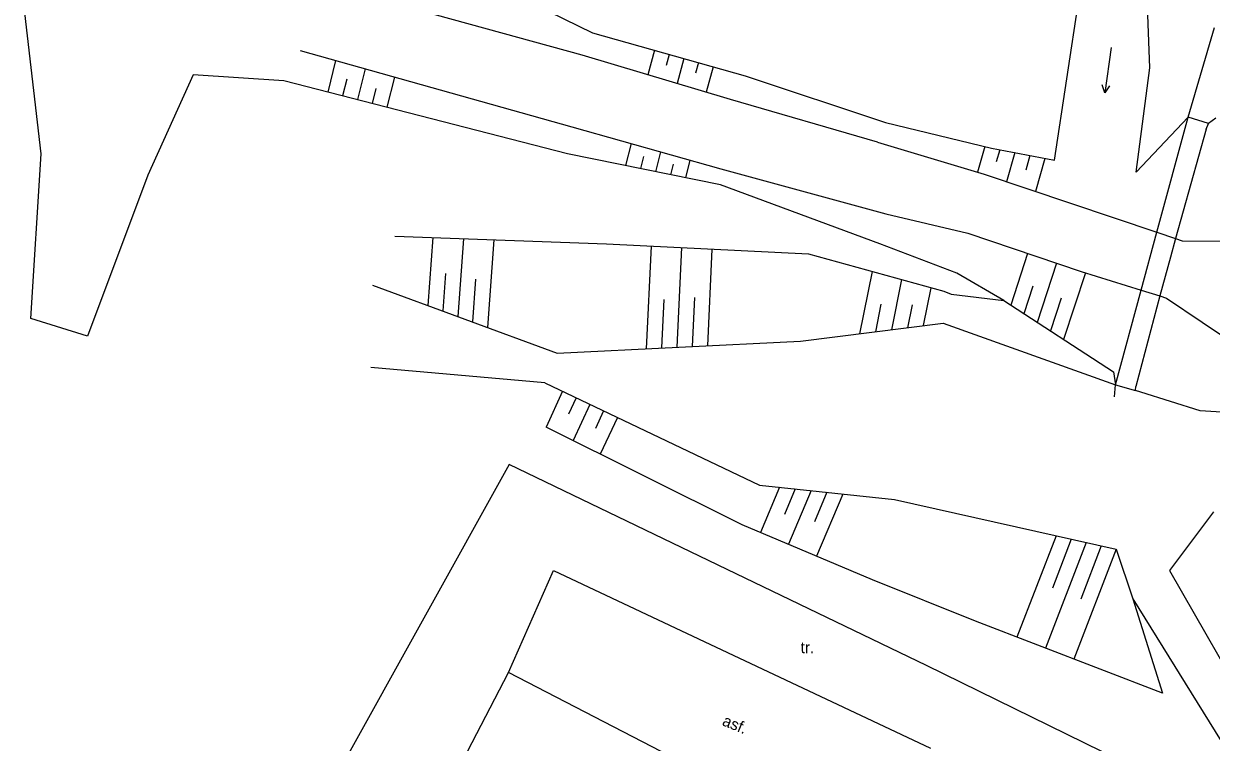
# Model space of a CAD drawing. Extents: x -794191 to -788944, y -1117087 to -1105044.
# Drawn here: x -790359.9 to -790282, y -1111834.4 to -1111787.2 of the extents above; entities that cross this region are included whole.
import ezdxf

# ---------------------------------------------------------------- set-up
doc = ezdxf.new("R2010")
doc.units = 0
for name, color, linetype in [('Doplněk polohopisu', 7, 'Continuous'), ('Hranice - ploty_ zdi', 7, 'Continuous'), ('Komunikace', 7, 'Continuous'), ('Pomocné popisy', 7, 'Continuous'), ('Stavební objekty', 7, 'Continuous'), ('Výškopis', 7, 'Continuous'), ('Značky druhů pozemků', 7, 'Continuous')]:
    doc.layers.add(name, color=color, linetype=linetype)

msp = doc.modelspace()

# ---------------------------------------------------------------- linework, layer by layer
at = {"layer": 'Doplněk polohopisu'}
for p, q in [((-790299.53, -1111804.77), (-790299.05, -1111804.96)), ((-790299.05, -1111804.96), (-790295.6, -1111805.38))]:
    msp.add_line(p, q, dxfattribs=at)
at = {"layer": 'Hranice - ploty_ zdi'}
for p, q in [((-790283.5, -1111793.35), (-790281.76, -1111787.46)), ((-790288.26, -1111810.91), (-790286.95, -1111811.28)), ((-790286.95, -1111811.28), (-790286.92, -1111811.01)), ((-790328.05, -1111816.14), (-790344.67, -1111845.99)), ((-790300.68, -1111829.32), (-790328.05, -1111816.14)), ((-790282.07, -1111838.44), (-790300.68, -1111829.32))]:
    msp.add_line(p, q, dxfattribs=at)
for points in [[(-790288.32, -1111811.7), (-790288.26, -1111810.91), (-790286.57, -1111804.7), (-790285.56, -1111800.88), (-790283.5, -1111793.35)], [(-790282.32, -1111794.13), (-790282.15, -1111793.76), (-790283.5, -1111793.35)], [(-790282.32, -1111794.13), (-790284.32, -1111801.3), (-790284.66, -1111802.53)], [(-790284.66, -1111802.53), (-790285.36, -1111805.07), (-790286.92, -1111811.01)]]:
    msp.add_lwpolyline(points, dxfattribs=at)
at = {"layer": 'Komunikace'}
msp.add_line((-790287.12, -1111824.96), (-790281.32, -1111834.29), dxfattribs=at)
for points in [[(-790281.84, -1111819.25), (-790284.71, -1111823.1), (-790279.09, -1111832.9)], [(-790328.11, -1111829.78), (-790325.14, -1111823.09), (-790300.4, -1111834.76)]]:
    msp.add_lwpolyline(points, dxfattribs=at)
at = {"layer": 'Stavební objekty'}
msp.add_line((-790339.54, -1111851.86), (-790328.11, -1111829.78), dxfattribs=at)
msp.add_lwpolyline([(-790339.54, -1111851.86), (-790329.07, -1111857.3), (-790328.18, -1111857.64), (-790325.33, -1111852.24), (-790319.61, -1111841.2), (-790316.82, -1111835.63), (-790328.11, -1111829.78)], dxfattribs=at)
at = {"layer": 'Výškopis'}
for p, q in [((-790292.26, -1111796.17), (-790289.79, -1111779.85)), ((-790286.02, -1111790.1), (-790286.31, -1111781.72)), ((-790323.27, -1111789.28), (-790340.36, -1111784.56)), ((-790358.77, -1111795.75), (-790359.92, -1111785.93)), ((-790327.38, -1111785.46), (-790322.58, -1111787.81)), ((-790322.58, -1111787.81), (-790312.56, -1111790.62)), ((-790341.77, -1111788.97), (-790323.94, -1111793.98)), ((-790318.53, -1111788.95), (-790318.96, -1111790.56)), ((-790339.45, -1111789.62), (-790339.96, -1111791.69)), ((-790313.54, -1111792.18), (-790323.27, -1111789.28)), ((-790317.56, -1111789.22), (-790317.76, -1111789.94)), ((-790316.6, -1111789.49), (-790317.04, -1111791.14)), ((-790315.64, -1111789.76), (-790315.82, -1111790.45)), ((-790348.8, -1111790.57), (-790351.78, -1111797.14)), ((-790342.85, -1111790.95), (-790348.8, -1111790.57)), ((-790337.52, -1111790.16), (-790338.02, -1111792.19)), ((-790335.59, -1111790.71), (-790336.09, -1111792.69)), ((-790314.67, -1111790.03), (-790315.12, -1111791.71)), ((-790312.56, -1111790.62), (-790303.35, -1111793.68)), ((-790286.91, -1111796.96), (-790286.02, -1111790.1)), ((-790324.24, -1111795.74), (-790342.85, -1111790.95)), ((-790338.72, -1111790.84), (-790338.99, -1111791.94)), ((-790336.81, -1111791.45), (-790337.06, -1111792.44)), ((-790303.88, -1111794.98), (-790313.54, -1111792.18)), ((-790303.35, -1111793.68), (-790296.41, -1111795.38)), ((-790286.91, -1111796.96), (-790283.5, -1111793.35)), ((-790281.68, -1111793.41), (-790282.15, -1111793.76)), ((-790323.94, -1111793.98), (-790314.16, -1111796.73)), ((-790320.06, -1111795.07), (-790320.42, -1111796.52)), ((-790303.88, -1111794.98), (-790296.88, -1111797.09)), ((-790296.84, -1111795.27), (-790297.32, -1111796.96)), ((-790296.41, -1111795.38), (-790292.26, -1111796.17)), ((-790359.46, -1111806.55), (-790358.77, -1111795.75)), ((-790314.18, -1111797.79), (-790324.24, -1111795.74)), ((-790319.24, -1111795.93), (-790319.44, -1111796.72)), ((-790318.13, -1111795.61), (-790318.46, -1111796.92)), ((-790316.2, -1111796.16), (-790316.49, -1111797.32)), ((-790295.86, -1111795.48), (-790296.09, -1111796.27)), ((-790294.88, -1111795.67), (-790295.42, -1111797.58)), ((-790293.89, -1111795.86), (-790294.16, -1111796.81)), ((-790292.91, -1111796.05), (-790293.52, -1111798.22)), ((-790317.3, -1111796.42), (-790317.47, -1111797.12)), ((-790314.16, -1111796.73), (-790303.33, -1111799.68)), ((-790351.78, -1111797.14), (-790355.73, -1111807.72)), ((-790303.73, -1111801.65), (-790314.18, -1111797.79)), ((-790303.33, -1111799.68), (-790297.95, -1111800.96)), ((-790335.57, -1111801.15), (-790321.68, -1111801.66)), ((-790333.07, -1111801.24), (-790333.39, -1111805.7)), ((-790331.06, -1111801.32), (-790331.44, -1111806.42)), ((-790329.06, -1111801.39), (-790329.49, -1111807.14)), ((-790297.95, -1111800.96), (-790290.52, -1111803.46)), ((-790283.89, -1111801.45), (-790277.7, -1111801.5)), ((-790321.68, -1111801.66), (-790308.42, -1111802.31)), ((-790318.74, -1111801.8), (-790319.06, -1111808.54)), ((-790316.75, -1111801.9), (-790317.05, -1111808.44)), ((-790314.75, -1111802), (-790315.04, -1111808.34)), ((-790308.42, -1111802.31), (-790299.53, -1111804.77)), ((-790298.67, -1111803.57), (-790303.73, -1111801.65)), ((-790294.04, -1111802.28), (-790295.14, -1111805.68)), ((-790292.14, -1111802.92), (-790293.41, -1111806.81)), ((-790332.24, -1111803.61), (-790332.42, -1111806.06)), ((-790304.24, -1111803.47), (-790305.06, -1111807.56)), ((-790295.6, -1111805.38), (-790298.67, -1111803.57)), ((-790290.24, -1111803.55), (-790291.67, -1111807.93)), ((-790337.03, -1111804.37), (-790324.9, -1111808.82)), ((-790330.26, -1111803.98), (-790330.46, -1111806.78)), ((-790302.31, -1111804), (-790302.97, -1111807.29)), ((-790300.38, -1111804.54), (-790300.88, -1111807.02)), ((-790293.68, -1111804.43), (-790294.27, -1111806.24)), ((-790317.91, -1111805.31), (-790318.06, -1111808.49)), ((-790315.9, -1111805.18), (-790316.05, -1111808.39)), ((-790295.6, -1111805.38), (-790288.4, -1111810.06)), ((-790291.84, -1111805.23), (-790292.54, -1111807.37)), ((-790284.92, -1111805.21), (-790280.12, -1111808.46)), ((-790303.66, -1111805.61), (-790304.02, -1111807.42)), ((-790301.62, -1111805.66), (-790301.92, -1111807.16)), ((-790355.73, -1111807.72), (-790359.46, -1111806.55)), ((-790308.93, -1111808.05), (-790299.58, -1111806.86)), ((-790299.58, -1111806.86), (-790288.26, -1111810.91)), ((-790324.9, -1111808.82), (-790308.93, -1111808.05)), ((-790325.71, -1111810.78), (-790337.13, -1111809.78)), ((-790288.4, -1111810.06), (-790288.26, -1111810.91)), ((-790325.71, -1111810.78), (-790311.63, -1111817.49)), ((-790324.55, -1111811.33), (-790325.63, -1111813.69)), ((-790323.66, -1111811.76), (-790324.16, -1111812.83)), ((-790286.6, -1111811.39), (-790286.95, -1111811.28)), ((-790282.71, -1111812.62), (-790286.6, -1111811.39)), ((-790322.76, -1111812.19), (-790323.87, -1111814.57)), ((-790321.86, -1111812.62), (-790322.4, -1111813.78)), ((-790320.95, -1111813.05), (-790322.08, -1111815.46)), ((-790275.19, -1111813.07), (-790282.71, -1111812.62)), ((-790312.76, -1111820.09), (-790325.63, -1111813.69)), ((-790311.63, -1111817.49), (-790302.77, -1111818.44)), ((-790310.32, -1111817.63), (-790311.57, -1111820.59)), ((-790309.28, -1111817.74), (-790309.99, -1111819.42)), ((-790308.24, -1111817.85), (-790309.73, -1111821.37)), ((-790307.21, -1111817.96), (-790308.02, -1111819.89)), ((-790306.17, -1111818.08), (-790307.89, -1111822.15)), ((-790302.77, -1111818.44), (-790288.21, -1111821.69)), ((-790304.22, -1111823.7), (-790312.76, -1111820.09)), ((-790292.16, -1111820.81), (-790294.73, -1111827.47)), ((-790291.17, -1111821.03), (-790292.41, -1111824.25)), ((-790290.18, -1111821.25), (-790292.86, -1111828.19)), ((-790288.21, -1111821.69), (-790291, -1111828.91)), ((-790289.2, -1111821.47), (-790290.55, -1111824.98)), ((-790297.46, -1111826.42), (-790304.22, -1111823.7)), ((-790285.19, -1111831.14), (-790297.46, -1111826.42))]:
    msp.add_line(p, q, dxfattribs=at)
for points in [[(-790296.88, -1111797.09), (-790285.56, -1111800.88), (-790284.32, -1111801.3), (-790283.89, -1111801.45)], [(-790290.52, -1111803.46), (-790286.57, -1111804.7), (-790285.36, -1111805.07), (-790284.92, -1111805.21)], [(-790288.21, -1111821.69), (-790287.12, -1111824.96), (-790285.19, -1111831.14)]]:
    msp.add_lwpolyline(points, dxfattribs=at)
at = {"layer": 'Značky druhů pozemků'}
msp.add_line((-790288.55, -1111788.775), (-790288.97, -1111791.745), dxfattribs=at)
msp.add_lwpolyline([(-790288.653, -1111791.285), (-790288.97, -1111791.745), (-790289.149, -1111791.215)], dxfattribs=at)

# ---------------------------------------------------------------- texts
at = {"layer": 'Pomocné popisy'}
msp.add_text('tr.', height=0.75, dxfattribs=at).set_placement((-790308.93, -1111828.52))
msp.add_text('asf.', height=0.75, rotation=337.60539, dxfattribs=at).set_placement((-790314.13, -1111833.23))

doc.saveas('drawing.dxf')
